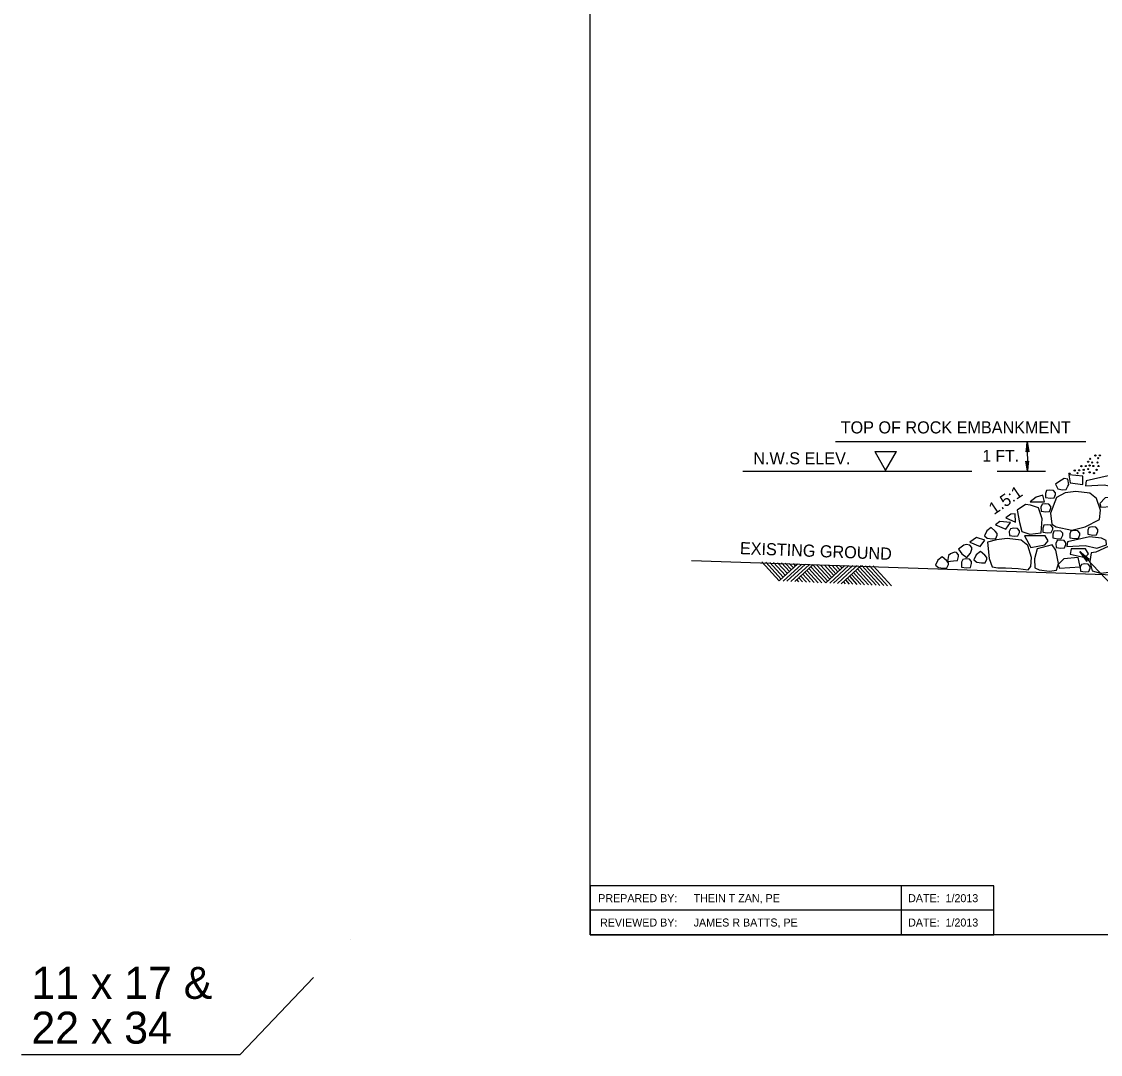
# Model space of a CAD drawing. Extents: x 2189223 to 2190097, y 563994 to 564498.
# Drawn here: x 2189223.4 to 2189459.3, y 564012.7 to 564238.4 of the extents above; entities that cross this region are included whole.
import ezdxf

# ---------------------------------------------------------------- set-up
doc = ezdxf.new("R2010")
doc.units = 0
for name, color, linetype in [('Default', 7, 'Continuous'), ('Exist XS Ground Line', 7, 'Continuous'), ('Geotech Sheets and Borders Cell', 7, 'Continuous'), ('Misc Plan Tools Cell', 7, 'Continuous'), ('Old_Level_18', 7, 'Continuous'), ('Old_Level_2', 7, 'Continuous')]:
    doc.layers.add(name, color=color, linetype=linetype)

msp = doc.modelspace()

# ---------------------------------------------------------------- linework, layer by layer
at = {"layer": 'Default'}
for p, q in [((2189401.39, 564146.62), (2189456.11, 564146.62)), ((2189454.83, 564122.61), (2189474.44, 564101.85)), ((2189385.28, 564120.33), (2189389.08, 564116.18)), ((2189386.13, 564120.28), (2189389.52, 564116.58)), ((2189386.99, 564120.24), (2189389.96, 564116.99)), ((2189387.84, 564120.2), (2189390.41, 564117.39)), ((2189388.69, 564120.15), (2189390.85, 564117.8)), ((2189389.08, 564116.18), (2189393.16, 564119.92)), ((2189389.55, 564120.11), (2189391.29, 564118.21)), ((2189389.92, 564116.14), (2189394, 564119.87)), ((2189390.4, 564120.06), (2189391.73, 564118.61)), ((2189390.77, 564116.1), (2189394.84, 564119.83)), ((2189391.26, 564120.02), (2189392.18, 564119.02)), ((2189391.62, 564116.07), (2189395.68, 564119.79)), ((2189392.11, 564119.97), (2189392.62, 564119.42)), ((2189392.47, 564116.03), (2189396.52, 564119.74)), ((2189392.97, 564119.93), (2189393.06, 564119.83)), ((2189394.24, 564117.65), (2189395.86, 564115.88)), ((2189394.68, 564118.06), (2189396.71, 564115.84)), ((2189395.13, 564118.46), (2189397.56, 564115.8)), ((2189395.57, 564118.87), (2189398.41, 564115.77)), ((2189396.01, 564119.27), (2189399.25, 564115.73)), ((2189396.45, 564119.68), (2189399.7, 564116.14)), ((2189397.24, 564119.71), (2189400.14, 564116.54)), ((2189398.1, 564119.66), (2189400.58, 564116.95)), ((2189398.94, 564119.62), (2189401.03, 564117.35)), ((2189399.25, 564115.73), (2189403.43, 564119.55)), ((2189399.78, 564119.6), (2189401.47, 564117.76)), ((2189400.1, 564115.69), (2189404.32, 564119.55)), ((2189400.62, 564119.58), (2189401.91, 564118.16)), ((2189400.95, 564115.66), (2189405.2, 564119.55)), ((2189402.35, 564118.57), (2189401.44, 564119.56)), ((2189401.8, 564115.62), (2189403.99, 564117.63)), ((2189402.26, 564119.56), (2189402.8, 564118.97)), ((2189402.65, 564115.58), (2189406.96, 564119.53)), ((2189403.08, 564119.55), (2189403.24, 564119.38)), ((2189404.07, 564117.7), (2189406.08, 564119.54)), ((2189404.86, 564117.61), (2189406.89, 564115.39)), ((2189405.3, 564118.01), (2189407.73, 564115.36)), ((2189405.75, 564118.42), (2189408.58, 564115.32)), ((2189406.18, 564118.82), (2189409.42, 564115.28)), ((2189406.62, 564119.22), (2189410.26, 564115.25)), ((2189407.14, 564119.53), (2189411.1, 564115.21)), ((2189407.96, 564119.51), (2189411.93, 564115.17)), ((2189408.79, 564119.48), (2189412.77, 564115.14)), ((2189409.63, 564119.45), (2189413.61, 564115.1)), ((2189392.91, 564116.43), (2189393.32, 564115.99)), ((2189393.35, 564116.84), (2189394.17, 564115.95)), ((2189393.8, 564117.25), (2189395.01, 564115.92)), ((2189403.09, 564115.99), (2189403.49, 564115.54)), ((2189403.53, 564116.39), (2189404.34, 564115.51)), ((2189405.19, 564115.47), (2189403.97, 564116.8)), ((2189404.42, 564117.2), (2189406.04, 564115.43))]:
    msp.add_line(p, q, dxfattribs=at)
for points in [[(2189347.77, 564405.93), (2189877.15, 564405.93), (2189877.15, 564038.89), (2189347.77, 564038.89)], [(2189452.68, 564137.59), (2189455.47, 564137.24), (2189455.42, 564139.06), (2189452.41, 564139.33)], [(2189456.03, 564136.96), (2189460.08, 564137.21), (2189462.62, 564136.66), (2189464.75, 564137.37), (2189464.65, 564138.33), (2189463.63, 564138.78), (2189461, 564139.14), (2189456.18, 564138.02)], [(2189452.38, 564137.27), (2189452.19, 564138.45), (2189451.39, 564138.57), (2189450.23, 564137.83), (2189449.48, 564137.33), (2189449.97, 564136.29), (2189451.02, 564136.12), (2189451.83, 564136.18), (2189452.14, 564136.92)], [(2189443.94, 564133.47), (2189447.08, 564133.49), (2189446.68, 564134.94), (2189445.27, 564134.46)], [(2189449.49, 564135.46), (2189449.05, 564135.95), (2189448.26, 564136.02), (2189447.53, 564135.91), (2189447.28, 564135.29), (2189447.31, 564134.43), (2189448.36, 564134.26), (2189449.17, 564134.32), (2189449.48, 564135.05)], [(2189463.52, 564134.6), (2189460.36, 564134.36), (2189459.15, 564133.09), (2189459.41, 564132.3), (2189463.93, 564132.59)], [(2189442.9, 564132.9), (2189441.12, 564131.63), (2189441.57, 564128.98), (2189442.08, 564126.95), (2189443.9, 564126.4), (2189446.33, 564126.7), (2189446.54, 564129.73), (2189445.78, 564132.14), (2189444, 564132.72)], [(2189448.49, 564132.47), (2189448.05, 564132.96), (2189447.26, 564133.03), (2189446.54, 564132.92), (2189446.29, 564132.3), (2189446.32, 564131.44), (2189447.37, 564131.27), (2189448.17, 564131.33), (2189448.49, 564132.06)], [(2189438.64, 564129.98), (2189440.73, 564129.02), (2189440.68, 564130.84), (2189439.72, 564130.79)], [(2189436.75, 564126.57), (2189436.31, 564127.05), (2189435.4, 564127.84), (2189434.46, 564127.14), (2189433.95, 564126.04), (2189434.57, 564125.53), (2189435.63, 564125.37), (2189436.43, 564125.42), (2189436.74, 564126.16)], [(2189436.36, 564128.44), (2189438.59, 564127.52), (2189439.62, 564128.95), (2189437.34, 564129.15)], [(2189441.58, 564127.16), (2189441.14, 564127.64), (2189440.35, 564127.71), (2189439.63, 564127.6), (2189439.38, 564126.98), (2189439.41, 564126.12), (2189440.46, 564125.96), (2189441.26, 564126.01), (2189441.58, 564126.75)], [(2189448.88, 564127.89), (2189448.44, 564128.37), (2189447.65, 564128.44), (2189446.93, 564128.33), (2189446.68, 564127.71), (2189446.71, 564126.85), (2189447.76, 564126.69), (2189448.56, 564126.74), (2189448.88, 564127.48)], [(2189451.07, 564126.6), (2189450.63, 564127.09), (2189449.84, 564127.16), (2189449.12, 564127.05), (2189448.87, 564126.43), (2189448.9, 564125.57), (2189449.95, 564125.4), (2189450.75, 564125.46), (2189451.07, 564126.19)], [(2189454.78, 564126.63), (2189454.35, 564127.12), (2189453.55, 564127.19), (2189452.83, 564127.08), (2189452.58, 564126.46), (2189452.61, 564125.6), (2189453.66, 564125.43), (2189454.47, 564125.49), (2189454.78, 564126.22)], [(2189458.75, 564127.41), (2189458.31, 564127.9), (2189457.52, 564127.97), (2189456.8, 564127.85), (2189456.54, 564127.24), (2189456.57, 564126.38), (2189457.63, 564126.21), (2189458.43, 564126.27), (2189458.75, 564127)], [(2189430.75, 564124.62), (2189432.97, 564123.69), (2189434.01, 564125.12), (2189432.18, 564125.7)], [(2189444.11, 564123.5), (2189447.11, 564124.05), (2189447.87, 564124.91), (2189447.21, 564126), (2189442.69, 564126)], [(2189451.77, 564124.54), (2189451.34, 564125.02), (2189450.54, 564125.09), (2189449.82, 564124.98), (2189449.57, 564124.36), (2189449.6, 564123.5), (2189450.65, 564123.34), (2189451.46, 564123.39), (2189451.77, 564124.13)], [(2189451.92, 564123.67), (2189455.97, 564123.92), (2189458.51, 564123.37), (2189460.63, 564124.08), (2189460.53, 564125.04), (2189459.52, 564125.49), (2189456.88, 564125.85), (2189452.07, 564124.73)], [(2189428.26, 564121.91), (2189427.82, 564122.39), (2189427.39, 564122.5), (2189426.5, 564122.1), (2189426.06, 564121.73), (2189425.85, 564120.45), (2189427.15, 564120.56), (2189428.03, 564120.63), (2189428.26, 564121.5)], [(2189431.15, 564123.5), (2189430.71, 564123.99), (2189429.98, 564124.12), (2189429.42, 564123.97), (2189428.27, 564123.09), (2189429, 564122.13), (2189430.11, 564121.27), (2189430.92, 564122.23), (2189431.15, 564123.09)], [(2189434.43, 564121.32), (2189434, 564121.8), (2189433.09, 564122.59), (2189432.15, 564121.89), (2189431.64, 564120.79), (2189432.26, 564120.28), (2189433.31, 564120.12), (2189434.12, 564120.17), (2189434.43, 564120.91)], [(2189445.47, 564123.18), (2189444.91, 564121.01), (2189444.99, 564119.04), (2189445.92, 564118.58), (2189448.16, 564118.34), (2189449.69, 564118.52), (2189450.13, 564119.96), (2189449.58, 564122.9), (2189448.75, 564124.06)], [(2189452.71, 564122.04), (2189455.95, 564121.28), (2189456.71, 564122.13), (2189456.04, 564123.23), (2189452.9, 564123.23)], [(2189458.26, 564122.48), (2189457.31, 564122.3), (2189456.97, 564120.43), (2189457.48, 564118.41), (2189459.3, 564117.85), (2189463.76, 564118.4), (2189463.73, 564120.47), (2189463.3, 564123.03), (2189460.97, 564123.67)], [(2189426.07, 564120.16), (2189425.63, 564120.64), (2189424.72, 564121.43), (2189423.78, 564120.73), (2189423.27, 564119.63), (2189423.89, 564119.12), (2189424.95, 564118.96), (2189425.75, 564119.01), (2189426.07, 564119.75)], [(2189431.13, 564120.42), (2189430.7, 564120.91), (2189429.9, 564120.98), (2189429.18, 564120.86), (2189428.93, 564120.25), (2189428.9, 564119.16), (2189430.02, 564119.07), (2189430.9, 564119.15), (2189431.13, 564120.01)], [(2189454.45, 564121.28), (2189451.29, 564121.04), (2189450.08, 564119.77), (2189450.34, 564118.98), (2189454.86, 564119.27)], [(2189457.09, 564119.36), (2189456.65, 564119.85), (2189455.86, 564119.92), (2189455.13, 564119.8), (2189454.88, 564119.18), (2189454.91, 564118.33), (2189455.96, 564118.16), (2189456.77, 564118.21), (2189457.08, 564118.95)]]:
    msp.add_lwpolyline(points, close=True, dxfattribs=at)
for points in [[(2189459.07, 564129.58), (2189459.08, 564129.6), (2189459.28, 564131.61), (2189458.42, 564134.22), (2189456.99, 564135.36), (2189453.94, 564135.74), (2189451.61, 564135.46), (2189449.66, 564134.41), (2189448.37, 564131), (2189448.66, 564128.61), (2189449.61, 564128), (2189453.03, 564127.26)], [(2189453.03, 564127.26), (2189455.97, 564127.99), (2189459.07, 564129.58)], [(2189443.52, 564118.58), (2189444.06, 564119.31), (2189444.25, 564121.32), (2189443.4, 564123.94), (2189441.97, 564125.08), (2189438.92, 564125.46), (2189436.59, 564125.17), (2189434.59, 564124.68), (2189434.98, 564121.08), (2189435.63, 564119.24), (2189436.84, 564119.03), (2189438.58, 564119.03)], [(2189438.58, 564119.03), (2189441.29, 564118.89), (2189443.52, 564118.58)]]:
    msp.add_lwpolyline(points, dxfattribs=at)
for centre in [(2189458.19, 564143.57), (2189459.16, 564143.61), (2189455.14, 564141.24), (2189456.09, 564141.28), (2189456.61, 564142.23), (2189456.94, 564141.39), (2189457.04, 564142.87), (2189457.48, 564142.07), (2189457.76, 564141.28), (2189458.65, 564142.07), (2189458.8, 564142.99), (2189458.88, 564141.29), (2189452.52, 564139.62), (2189453.68, 564140.31), (2189454.28, 564139.74), (2189454.65, 564140.35), (2189455.59, 564139.72), (2189455.64, 564140.47), (2189456.63, 564140.62), (2189456.94, 564139.91), (2189457.9, 564139.72), (2189458.46, 564140.46)]:
    msp.add_circle(centre, 0.127, dxfattribs=at)
at = {"layer": 'Exist XS Ground Line'}
msp.add_line((2189369.91, 564120.67), (2189520.23, 564115.59), dxfattribs=at)
at = {"layer": 'Geotech Sheets and Borders Cell'}
for p, q in [((2189415.83, 564038.89), (2189415.83, 564049.53)), ((2189435.98, 564044.21), (2189347.77, 564044.21)), ((2189295.27, 564037.74), (2189295.27, 564037.74))]:
    msp.add_line(p, q, dxfattribs=at)
msp.add_lwpolyline([(2189435.98, 564049.53), (2189347.77, 564049.53), (2189347.77, 564038.89), (2189435.98, 564038.89)], close=True, dxfattribs=at)
msp.add_lwpolyline([(2189223.42, 564012.73), (2189271.18, 564012.73), (2189287.26, 564029.52)], dxfattribs=at)
at = {"layer": 'Misc Plan Tools Cell'}
for p, q in [((2189440.24, 564146.62), (2189445.84, 564146.62)), ((2189443.31, 564146.62), (2189443.02, 564144.42)), ((2189443.31, 564146.62), (2189443.06, 564144.46)), ((2189443.1, 564144.5), (2189443.31, 564146.62)), ((2189443.31, 564146.62), (2189443.14, 564144.54)), ((2189443.19, 564144.59), (2189443.31, 564146.62)), ((2189443.31, 564146.62), (2189443.23, 564144.62)), ((2189443.27, 564144.66), (2189443.31, 564146.62)), ((2189443.31, 564146.62), (2189443.61, 564144.42)), ((2189443.57, 564144.46), (2189443.31, 564146.62)), ((2189443.31, 564146.62), (2189443.53, 564144.5)), ((2189443.48, 564144.54), (2189443.31, 564146.62)), ((2189443.31, 564146.62), (2189443.44, 564144.59)), ((2189443.4, 564144.62), (2189443.31, 564146.62)), ((2189443.31, 564146.62), (2189443.36, 564144.66)), ((2189443.31, 564144.7), (2189443.31, 564146.62)), ((2189443.31, 564146.62), (2189443.32, 564140.18)), ((2189443.31, 564144.7), (2189443.02, 564144.42)), ((2189443.61, 564144.42), (2189443.31, 564144.7)), ((2189443.32, 564140.18), (2189443.02, 564142.38)), ((2189443.02, 564142.38), (2189443.32, 564142.09)), ((2189443.06, 564142.34), (2189443.32, 564140.18)), ((2189443.32, 564140.18), (2189443.1, 564142.3)), ((2189443.15, 564142.26), (2189443.32, 564140.18)), ((2189443.32, 564140.18), (2189443.19, 564142.21)), ((2189443.23, 564142.18), (2189443.32, 564140.18)), ((2189443.32, 564140.18), (2189443.27, 564142.13)), ((2189443.32, 564140.18), (2189443.61, 564142.38)), ((2189443.32, 564142.09), (2189443.61, 564142.38)), ((2189443.32, 564140.18), (2189443.57, 564142.34)), ((2189443.53, 564142.3), (2189443.32, 564140.18)), ((2189443.32, 564140.18), (2189443.49, 564142.26)), ((2189443.44, 564142.21), (2189443.32, 564140.18)), ((2189443.32, 564140.18), (2189443.4, 564142.18)), ((2189443.36, 564142.13), (2189443.32, 564140.18)), ((2189443.32, 564142.09), (2189443.32, 564140.18)), ((2189436.74, 564140.18), (2189447.28, 564140.18))]:
    msp.add_line(p, q, dxfattribs=at)
at = {"layer": 'Old_Level_18'}
for p, q in [((2189409.96, 564144.43), (2189414.71, 564144.43)), ((2189409.96, 564144.43), (2189412.34, 564140.31)), ((2189412.34, 564140.31), (2189414.71, 564144.43)), ((2189381.08, 564140.14), (2189431.2, 564140.14))]:
    msp.add_line(p, q, dxfattribs=at)
at = {"layer": 'Old_Level_2'}
for p, q in [((2189454.83, 564122.61), (2189456.86, 564120.93)), ((2189454.83, 564122.61), (2189456.34, 564120.45)), ((2189456.35, 564120.52), (2189454.83, 564122.61)), ((2189454.83, 564122.61), (2189456.35, 564120.59)), ((2189456.36, 564120.66), (2189454.83, 564122.61)), ((2189454.83, 564122.61), (2189456.36, 564120.73)), ((2189456.37, 564120.8), (2189454.83, 564122.61)), ((2189454.83, 564122.61), (2189456.37, 564120.87)), ((2189456.37, 564120.94), (2189454.83, 564122.61)), ((2189456.44, 564120.94), (2189454.83, 564122.61)), ((2189454.83, 564122.61), (2189456.51, 564120.94)), ((2189456.58, 564120.94), (2189454.83, 564122.61)), ((2189454.83, 564122.61), (2189456.65, 564120.94)), ((2189456.72, 564120.94), (2189454.83, 564122.61)), ((2189454.83, 564122.61), (2189456.79, 564120.93)), ((2189456.34, 564120.45), (2189456.37, 564120.94)), ((2189456.37, 564120.94), (2189456.86, 564120.93))]:
    msp.add_line(p, q, dxfattribs=at)

# ---------------------------------------------------------------- texts
at = {"layer": 'Default'}
for s, p in [('TOP OF ROCK EMBANKMENT ', (2189402.51, 564148.41)), ('N.W.S ELEV.', (2189383.4, 564141.65))]:
    msp.add_text(s, height=2.6459, dxfattribs=at).set_placement(p)
msp.add_text('EXISTING GROUND', height=2.6459, rotation=357.8135, dxfattribs=at).set_placement((2189380.44, 564122.05))
at = {"layer": 'Geotech Sheets and Borders Cell'}
for s, height, p in [('PREPARED BY:', 1.75, (2189349.5, 564045.99)), ('THEIN T ZAN, PE', 1.75, (2189370.36, 564045.99)), ('DATE:', 1.75, (2189417.25, 564045.99)), ('1/2013', 1.75, (2189425.43, 564045.99)), ('REVIEWED BY:', 1.75, (2189349.9, 564040.67)), ('JAMES R BATTS, PE', 1.75, (2189370.36, 564040.67)), ('DATE:', 1.75, (2189417.25, 564040.67)), ('1/2013', 1.75, (2189425.43, 564040.67)), ('11 x 17 &', 7, (2189225.57, 564024.87)), ('22 x 34', 7, (2189225.57, 564015.07))]:
    msp.add_text(s, height=height, dxfattribs=at).set_placement(p)
at = {"layer": 'Misc Plan Tools Cell'}
msp.add_text('1 FT.', height=2.566, dxfattribs=at).set_placement((2189433.49, 564142.25))
at = {"layer": 'Old_Level_2'}
msp.add_text('1.5:1', height=2.646, rotation=34.0666, dxfattribs=at).set_placement((2189436.02, 564130.54))

doc.saveas('drawing.dxf')
